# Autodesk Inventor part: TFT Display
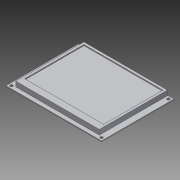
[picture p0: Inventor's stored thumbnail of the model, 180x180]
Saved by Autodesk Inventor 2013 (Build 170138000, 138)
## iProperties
Created: 2012-10
Part Number: TFT Display
Material: PPS-Kunststoff
Document SubType Name: Modeling
Designer: rYan
Mass: 35.8403 g
Surface Area: 132.087 cm^2
Volume: 21.8939 cm^3
Density: 1.637 g/cm^3
Author: rYan
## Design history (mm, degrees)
sketch "Skizze1"
  geometry: L1 (43.5, -33)-(-43.5, -33); L2 (-43.5, -33)-(-43.5, 33); L3 (-43.5, 33)-(43.5, 33); L4 (43.5, 33)-(43.5, -33); L5 (0, 46.2)-(0, -46.2) reference; L6 (-60.9, 0)-(60.9, 0) reference; 1 further point
  constraints: 8 end point, 2 parallel, 1 horizontal, 1 perpendicular, 2 other
  dimensions: "d0" = 87 distance of L2.end L3.end; "d1" = 66 distance of L1.end L2.end
extrude "Extrusion1" new body sketch "Skizze1" distance "d2" = 0.8; taper "d3" = 0 deg
sketch "Skizze4"
  geometry: L1 (43.5, 33)-(-43.5, 33) reference; L2 (-38, 32.5)-(38, 32.5); L3 (38, 32.5)-(38, -29.5); L4 (38, -29.5)-(-38, -29.5); L5 (-38, -29.5)-(-38, 32.5); L6 (0, 46.2)-(0, -46.2) reference; 1 further point
  constraints: 8 end point, 2 parallel, 1 horizontal, 1 perpendicular, 1 other
  dimensions: "d9" = 76 distance of L3.end L4.end; "d10" = 62 distance of L2.end L3.end; "d11" = 0.5 distance between parallel lines of L1 L2
extrude "Extrusion3" join sketch "Skizze4" distance "d12" = 4.5; taper "d13" = 0 deg
sketch "Skizze5"
  geometry: L1 (38, 32.5)-(-38, 32.5) reference; L2 (-38, 32.5)-(-38, -29.5) reference; L3 (-36, 30.5)-(36, 30.5); L4 (36, 30.5)-(36, -23.5); L5 (36, -23.5)-(-36, -23.5); L6 (-36, -23.5)-(-36, 30.5); 1 further point
  constraints: 8 end point, 2 parallel, 1 horizontal, 1 perpendicular
  dimensions: "d14" = 72 distance of L4.end L5.end; "d15" = 54 distance of L3.end L4.end; "d16" = 2 distance between parallel lines of L2 L6; "d17" = 2 distance between parallel lines of L1 L3
extrude "Extrusion4" cut sketch "Skizze5" distance "d18" = 1; taper "d19" = 0 deg
sketch "Skizze6"
  geometry: L1 (0, 46.2)-(0, -46.2) reference; L2 (-60.904, 0)-(60.925, 0) reference; 5 further points
  constraints: 2 symmetric about line
  dimensions: "d20" = 61 distance of point (-41, -30.5) point (-41, 30.5); "d22" = 61 distance of point (41, -30.5) point (41, 30.5); "d23" = 82 distance of point (-41, 30.5) point (41, 30.5); "d24" = 82 distance of point (41, -30.5) point (-41, -30.5)
hole "Bohrung1" sketch "Skizze6" at (-41, 30.5), (-41, -30.5), (41, 30.5), (41, -30.5) diameter "d25" = 2.5; stored, may be unused: countersink angle "d29" = 90 deg, drill point angle "d31" = 118 deg; dims "d26" = 6, "d27" = 4, "d28" = 2, "d30" = 8
node "Volumenkörper1"
